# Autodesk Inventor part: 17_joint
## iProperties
Shininess: 20.0
Length Units: 11270
Angle Units: 11279
Time Units: 11290
Mass Units: 11283
Length Display Precision: 3
Angle Display Precision: 2
Created: 2000-10
Part Number: 17_joint
Material: Par défaut
Document SubType Name: Modélisation
Density: 0.0
Volumn: 0.0
Area: 0.0
PropertySet Name: Model Information
Control State: 0
Master: False
Checked Out: False
Author: Laurent GAUTHERON
